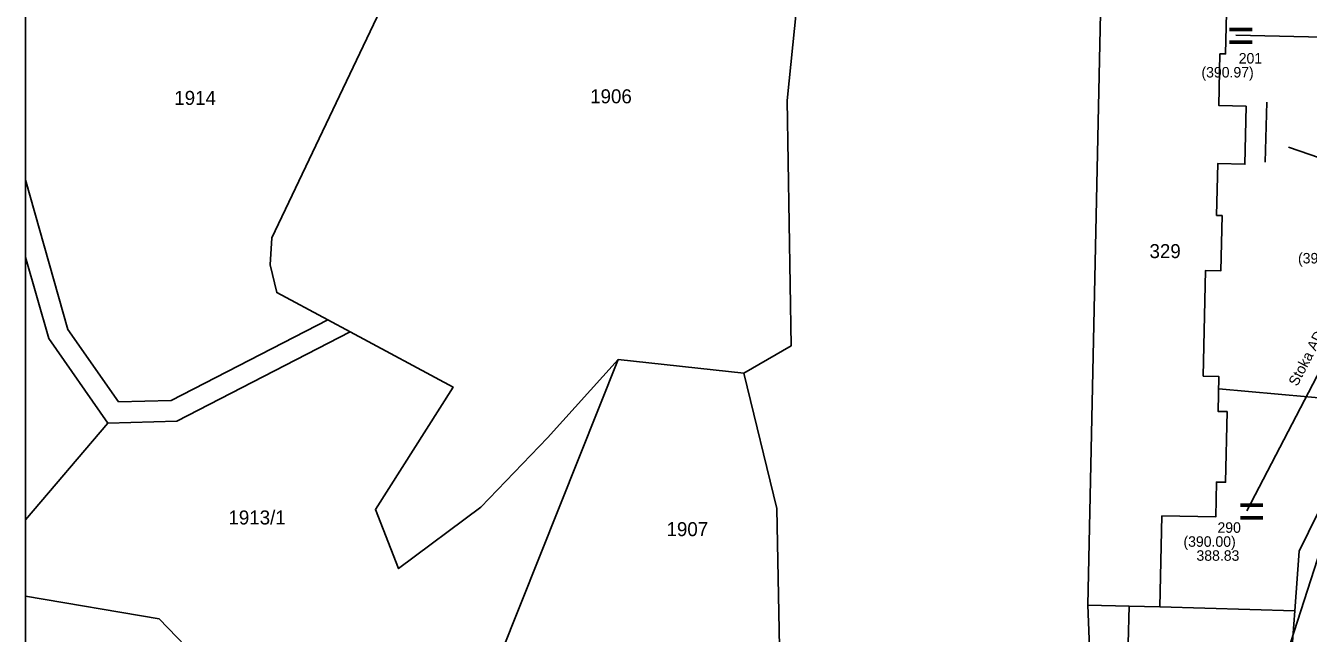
# Model space of a CAD drawing. Extents: x -564940 to -564406, y -1066466 to -1066072.
# Drawn here: x -564940.4 to -564757.1, y -1066298.6 to -1066211.8 of the extents above; entities that cross this region are included whole.
import ezdxf

# ---------------------------------------------------------------- set-up
doc = ezdxf.new("R2010")
doc.units = 0
for name, color, linetype in [('ft_g_5211', 7, 'Continuous'), ('ft_g_6101', 7, 'Continuous'), ('ft_g_6101_ft_g_6101_da_6108_gtc_da_6108', 7, 'Continuous'), ('ft_g_elektro_nn_vedeni', 7, 'Continuous'), ('ft_g_stoka', 7, 'Continuous'), ('ft_g_stoka_ft_g_stoka_da_oznaceni_gtc_da_6027', 7, 'Continuous'), ('ft_g_vrad', 7, 'Continuous'), ('ft_parcela_polygon', 7, 'Continuous'), ('ft_parcela_text', 7, 'Continuous'), ('ft_stavebni_objekt_polygon', 7, 'Continuous')]:
    doc.layers.add(name, color=color, linetype=linetype)

msp = doc.modelspace()

# ---------------------------------------------------------------- linework, layer by layer
at = {"layer": 'ft_g_5211'}
msp.add_line((-564744.61, -1066266), (-564769.91, -1066263.69), dxfattribs=at)
at = {"layer": 'ft_g_elektro_nn_vedeni'}
msp.add_line((-564763.08, -1066222.73), (-564763.3, -1066231.31), dxfattribs=at)
at = {"layer": 'ft_g_stoka'}
for p, q in [((-564767.49, -1066213.12), (-564732.02, -1066213.94)), ((-564732.02, -1066213.94), (-564764.38, -1066314.56)), ((-564765.93, -1066281.11), (-564749.04, -1066248.65))]:
    msp.add_line(p, q, dxfattribs=at)
at = {"layer": 'ft_g_vrad'}
msp.add_lwpolyline([(-564630.47, -1066273.68), (-564635.77, -1066272.37), (-564642.13, -1066271.08), (-564648.84, -1066268.35), (-564675.76, -1066261.05), (-564724.25, -1066241.46), (-564759.98, -1066229.13)], dxfattribs=at)
at = {"layer": 'ft_parcela_polygon'}
for p, q in [((-564940.44, -1066198.28), (-564940.44, -1066233.82)), ((-564940.44, -1066233.82), (-564940.44, -1066244.85)), ((-564940.44, -1066244.85), (-564940.44, -1066282.41)), ((-564940.44, -1066282.41), (-564940.44, -1066293.32)), ((-564940.44, -1066293.32), (-564940.44, -1066302.85))]:
    msp.add_line(p, q, dxfattribs=at)
for points in [[(-564940.44, -1066233.82), (-564934.39, -1066255.21), (-564927.16, -1066265.54), (-564919.63, -1066265.35), (-564897.28, -1066253.84), (-564904.57, -1066249.93), (-564905.48, -1066245.95), (-564905.26, -1066242.1), (-564887.36, -1066204.46), (-564886.17, -1066201.49), (-564888.16, -1066198.56), (-564890.55, -1066194.35), (-564905.62, -1066175.3), (-564912.35, -1066175.55), (-564916.37, -1066178.99), (-564919.38, -1066186.35), (-564922.96, -1066189.39), (-564928.61, -1066189.5), (-564940.34, -1066198.23), (-564940.44, -1066198.28)], [(-564887.36, -1066204.46), (-564905.26, -1066242.1), (-564905.48, -1066245.95), (-564904.57, -1066249.93), (-564897.28, -1066253.84), (-564894.07, -1066255.56), (-564879.36, -1066263.45), (-564890.46, -1066280.92), (-564887.16, -1066289.39), (-564875.41, -1066280.59), (-564865.85, -1066270.7), (-564855.75, -1066259.5), (-564837.82, -1066261.45), (-564831.07, -1066257.56), (-564831.63, -1066222.49), (-564827.92, -1066185.94)], [(-564827.92, -1066185.94), (-564831.63, -1066222.49), (-564831.07, -1066257.56), (-564837.82, -1066261.45), (-564833.11, -1066280.79), (-564832.6, -1066305.6), (-564833.32, -1066314.79), (-564836.37, -1066353.9), (-564836.61, -1066357.54), (-564836.7, -1066381.26), (-564836.11, -1066402.4), (-564830.86, -1066432.08), (-564832.2, -1066454.17), (-564832.49, -1066459.38), (-564832.78, -1066464.3), (-564829.72, -1066464.22), (-564829.56, -1066465.63)], [(-564789.13, -1066465.63), (-564787.74, -1066462.49), (-564785.83, -1066443.87), (-564781.17, -1066395.78), (-564778.57, -1066369.76), (-564776.75, -1066348.66), (-564776.2, -1066345.68), (-564779.17, -1066345.72), (-564786.65, -1066345.83), (-564788.66, -1066294.62), (-564786.51, -1066194.35), (-564785.71, -1066194.37), (-564785.51, -1066187.08), (-564780.98, -1066187.19), (-564781.14, -1066194.46), (-564776.02, -1066194.57), (-564768.77, -1066194.68), (-564751.79, -1066195.2)], [(-564786.51, -1066194.35), (-564788.66, -1066294.62), (-564782.77, -1066294.78), (-564778.35, -1066294.84), (-564778.07, -1066281.85), (-564770.38, -1066282.01), (-564770.27, -1066277.01), (-564768.97, -1066277.04), (-564768.76, -1066266.94), (-564770.05, -1066266.91), (-564769.95, -1066261.91), (-564772.15, -1066261.87), (-564771.83, -1066246.77), (-564769.63, -1066246.82), (-564769.46, -1066238.92), (-564770.26, -1066238.9), (-564770.1, -1066231.5), (-564766.2, -1066231.59), (-564766.03, -1066223.29), (-564769.92, -1066223.21), (-564769.77, -1066215.81), (-564768.97, -1066215.82), (-564768.8, -1066207.93)], [(-564768.8, -1066207.93), (-564768.97, -1066215.82), (-564769.77, -1066215.81), (-564769.92, -1066223.21), (-564766.03, -1066223.29), (-564766.2, -1066231.59), (-564770.1, -1066231.5), (-564770.26, -1066238.9), (-564769.46, -1066238.92), (-564769.63, -1066246.82), (-564771.83, -1066246.77), (-564772.15, -1066261.87), (-564769.95, -1066261.91), (-564770.05, -1066266.91), (-564768.76, -1066266.94), (-564768.97, -1066277.04), (-564770.27, -1066277.01), (-564770.38, -1066282.01), (-564778.07, -1066281.85), (-564778.35, -1066294.84), (-564759.08, -1066295.42), (-564758.45, -1066286.89), (-564735.99, -1066241.09)], [(-564940.44, -1066244.85), (-564937.14, -1066256.52), (-564928.69, -1066268.58), (-564918.86, -1066268.33), (-564894.07, -1066255.56), (-564897.28, -1066253.84), (-564919.63, -1066265.35), (-564927.16, -1066265.54), (-564934.39, -1066255.21), (-564940.44, -1066233.82)], [(-564735.99, -1066241.09), (-564758.45, -1066286.89), (-564759.08, -1066295.42), (-564760.78, -1066318.3), (-564763.14, -1066325.95), (-564775.57, -1066342.33), (-564776.2, -1066345.68), (-564776.75, -1066348.66), (-564778.57, -1066369.76), (-564781.17, -1066395.78), (-564785.83, -1066443.87), (-564787.74, -1066462.49), (-564787.89, -1066465.63)], [(-564940.44, -1066282.41), (-564928.69, -1066268.58), (-564937.14, -1066256.52), (-564940.44, -1066244.85)], [(-564940.44, -1066293.32), (-564921.38, -1066296.58), (-564915.01, -1066303.13), (-564892.71, -1066300.89), (-564891.3, -1066301.42), (-564879.77, -1066305.7), (-564877.59, -1066306.51), (-564872.55, -1066301.58), (-564855.75, -1066259.5), (-564865.85, -1066270.7), (-564875.41, -1066280.59), (-564887.16, -1066289.39), (-564890.46, -1066280.92), (-564879.36, -1066263.45), (-564894.07, -1066255.56), (-564918.86, -1066268.33), (-564928.69, -1066268.58), (-564940.44, -1066282.41)], [(-564940.44, -1066302.85), (-564933.09, -1066306.36), (-564923.79, -1066308.32), (-564915.01, -1066303.13), (-564921.38, -1066296.58), (-564940.44, -1066293.32)]]:
    msp.add_lwpolyline(points, dxfattribs=at)
for points in [[(-564872.55, -1066301.58), (-564832.6, -1066305.6), (-564833.11, -1066280.79), (-564837.82, -1066261.45), (-564855.75, -1066259.5)], [(-564786.65, -1066345.83), (-564779.17, -1066345.72), (-564782.89, -1066300.08), (-564782.77, -1066294.78), (-564788.66, -1066294.62)], [(-564763.14, -1066325.95), (-564760.78, -1066318.3), (-564759.08, -1066295.42), (-564778.35, -1066294.84), (-564782.77, -1066294.78), (-564782.89, -1066300.08), (-564779.17, -1066345.72), (-564776.2, -1066345.68), (-564775.57, -1066342.33)]]:
    msp.add_lwpolyline(points, close=True, dxfattribs=at)
at = {"layer": 'ft_stavebni_objekt_polygon'}
msp.add_lwpolyline([(-564786.51, -1066194.35), (-564788.66, -1066294.62), (-564782.77, -1066294.78), (-564778.35, -1066294.84), (-564778.07, -1066281.85), (-564770.38, -1066282.01), (-564770.27, -1066277.01), (-564768.97, -1066277.04), (-564768.76, -1066266.94), (-564770.05, -1066266.91), (-564769.95, -1066261.91), (-564772.15, -1066261.87), (-564771.83, -1066246.77), (-564769.63, -1066246.82), (-564769.46, -1066238.92), (-564770.26, -1066238.9), (-564770.1, -1066231.5), (-564766.2, -1066231.59), (-564766.03, -1066223.29), (-564769.92, -1066223.21), (-564769.77, -1066215.81), (-564768.97, -1066215.82), (-564768.8, -1066207.93)], dxfattribs=at)

# ---------------------------------------------------------------- texts
at = {"layer": 'ft_g_6101'}
for p in [(-564768.74, -1066215.62), (-564767.18, -1066283.61)]:
    msp.add_text('=', height=5, dxfattribs=at).set_placement(p)
at = {"layer": 'ft_g_6101_ft_g_6101_da_6108_gtc_da_6108'}
for s, p in [('201', (-564767.09, -1066217.19)), ('(390.97)', (-564772.42, -1066219.19)), ('(390.40)', (-564758.62, -1066245.77)), ('290', (-564770.13, -1066284.27)), ('(390.00)', (-564774.99, -1066286.27)), ('388.83', (-564773.13, -1066288.27))]:
    msp.add_text(s, height=1.5, dxfattribs=at).set_placement(p)
at = {"layer": 'ft_g_stoka_ft_g_stoka_da_oznaceni_gtc_da_6027'}
msp.add_text('Stoka ADa', height=1.5, rotation=62.5134, dxfattribs=at).set_placement((-564758.73, -1066263.42))
at = {"layer": 'ft_parcela_text'}
for s, p in [('1914', (-564919.2, -1066223.1)), ('1906', (-564859.77, -1066222.88)), ('329', (-564779.84, -1066245.01)), ('1913/1', (-564911.46, -1066283.08)), ('1907', (-564848.86, -1066284.75))]:
    msp.add_text(s, height=2, dxfattribs=at).set_placement(p)

doc.saveas('drawing.dxf')
